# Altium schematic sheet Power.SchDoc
size A3; CompanyName: Icoteq Ltd; Address1: Cambridge House; Address2: 1 Henry Street; Address3: Bath; Address4: BA1 1BT; DocumentNumber: Power Supplies; SheetNumber: 1
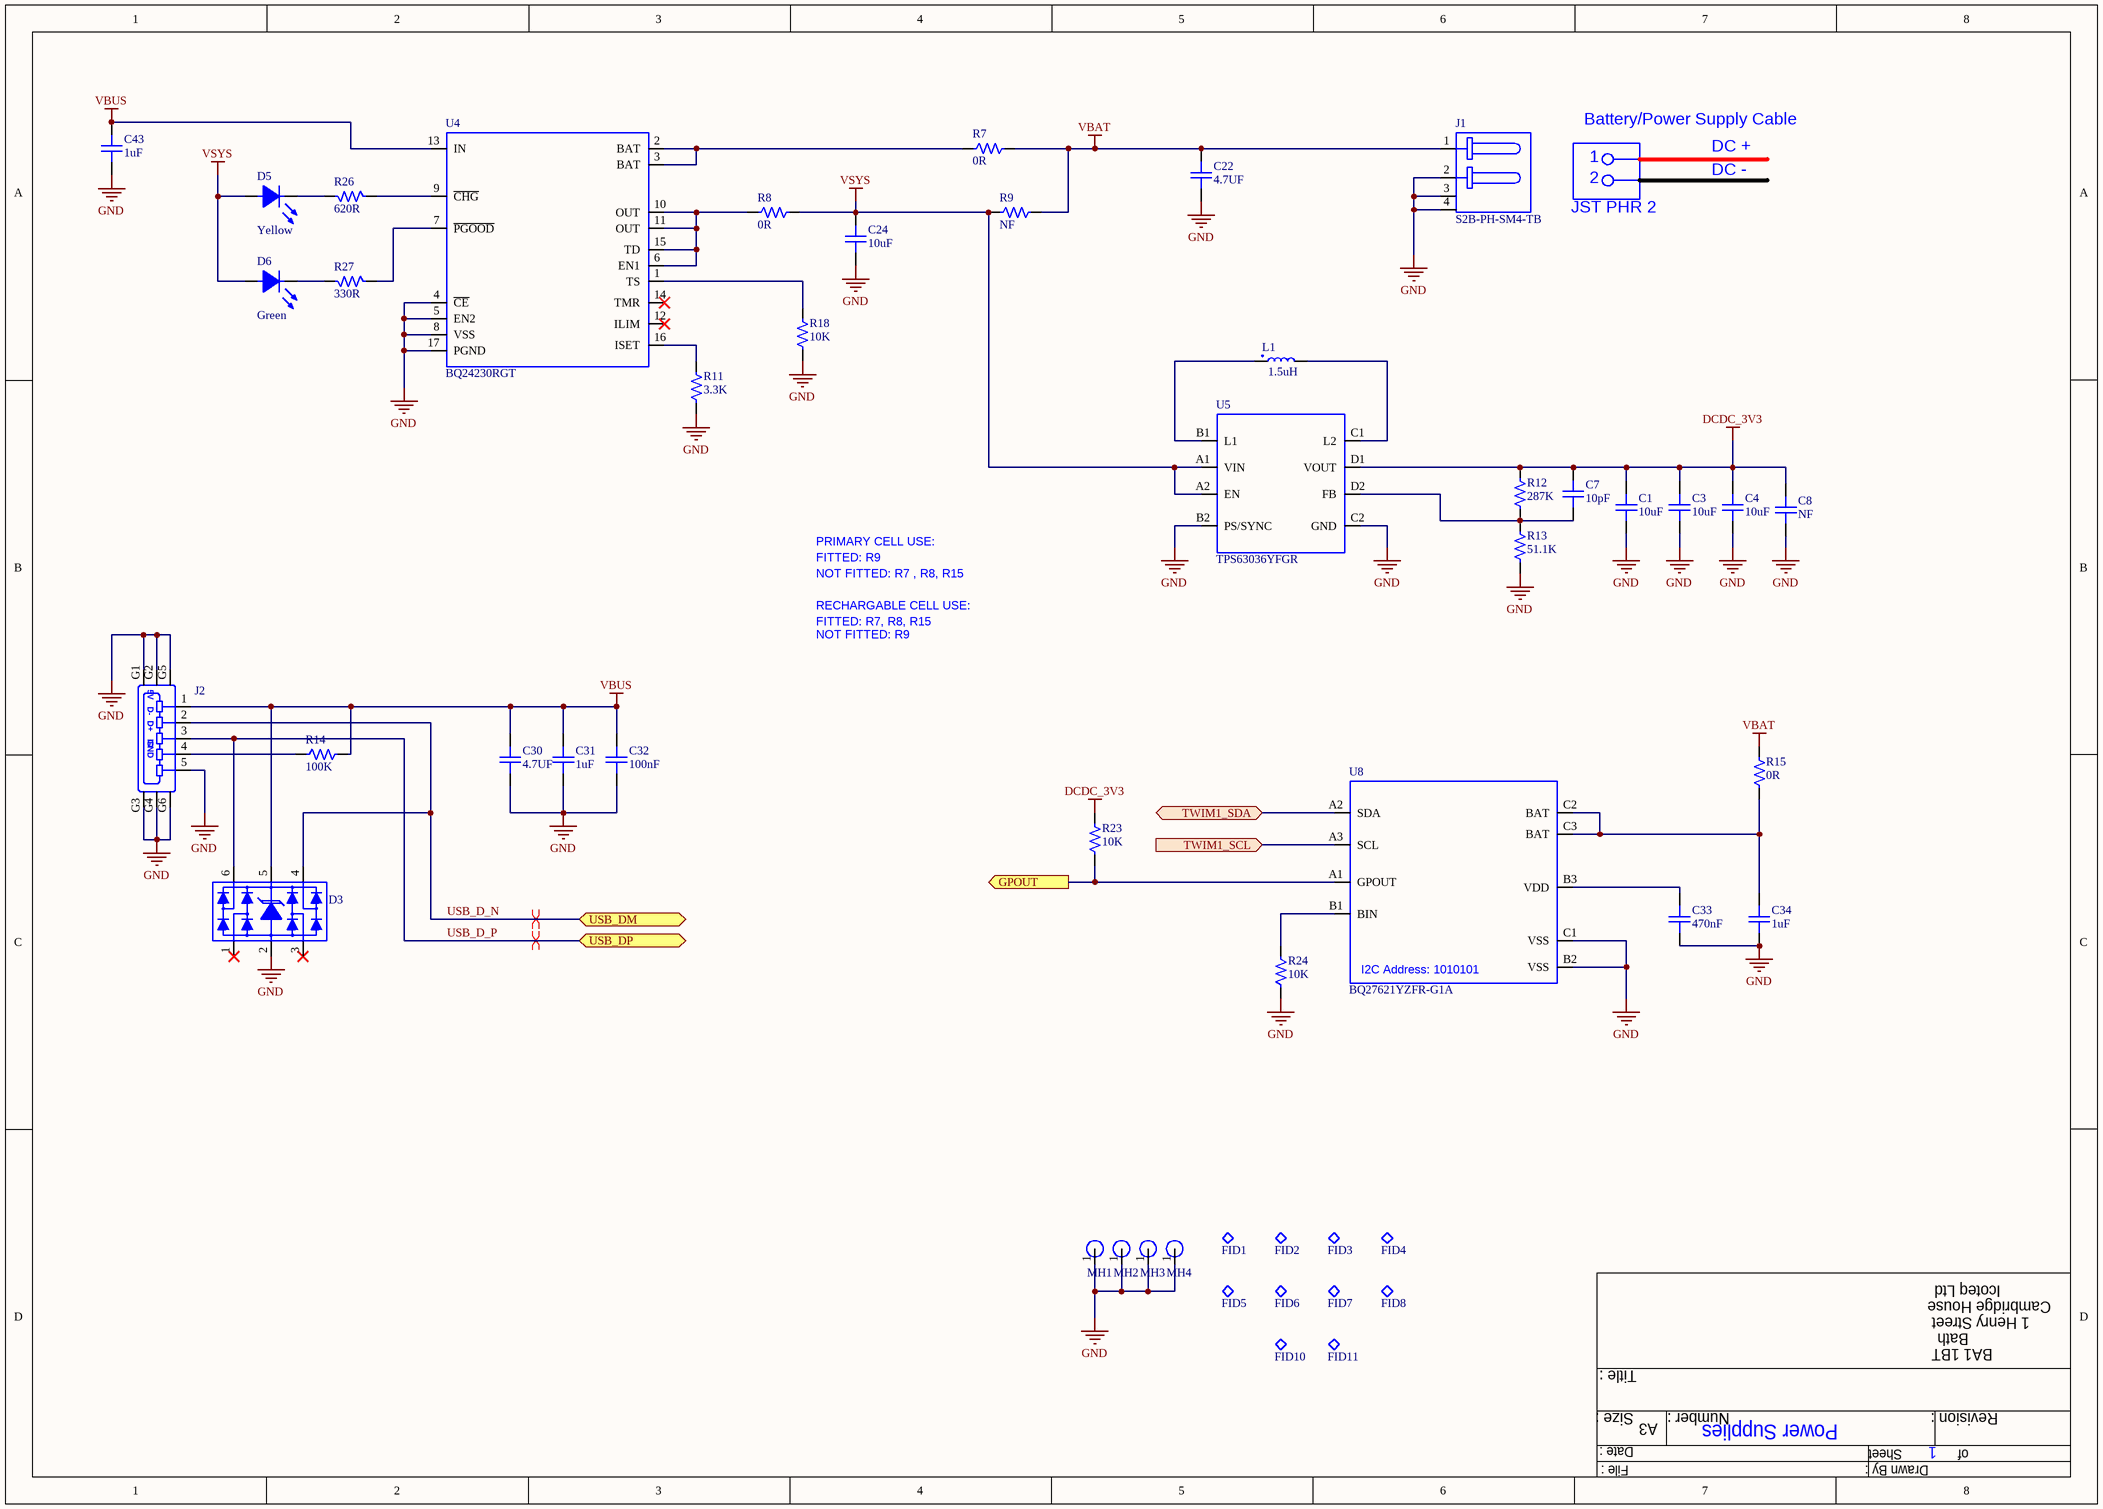
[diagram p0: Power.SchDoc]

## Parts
C1  value 10uF  [CAP0402N]  (hidden comment: 10UF 0402 6.3V 20% X5R)
C3  value 10uF  [CAP0402N]  (hidden comment: 10UF 0402 6.3V 20% X5R)
C4  value 10uF  [CAP0402N]  (hidden comment: 10UF 0402 6.3V 20% X5R)
C7  value 10pF  [Passive0201L]  (hidden comment: CAP CER 10PF 0201 25V 5% C0G)
C8  value NF  [CAP0402N_NF]  (hidden comment: CAP NF 0402)
C22  value 4.7UF  [CAP0402N]  (hidden comment: 4.7UF 0402 10V 20% X5R)
C24  value 10uF  [CAP0603N]  (hidden comment: 10UF 0603 16V 10% X5R)
C30  value 4.7UF  [CAP0402N]  (hidden comment: 4.7UF 0402 10V 20% X5R)
C31  value 1uF  [CAP0201L]  (hidden comment: 1UF 0201 10V 20% X5R)
C32  value 100nF  [CAP0201L]  (hidden comment: 100NF 0201 35V 10% X5R)
C33  value 470nF  [CAP0201L]  (hidden comment: 470NF 0201 16V 20% X5R)
C34  value 1uF  [CAP0201L]  (hidden comment: 1UF 0201 10V 20% X5R)
C43  value 1uF  [CAP0201L]  (hidden comment: 1UF 0201 10V 20% X5R)
D3  RCLAMP0504FBTCT  [SC70-6]  (value not drawn)
D5  Colour: Yellow  [DIOD0603N_YELLOW]  (hidden comment: LTST-C190KSKT)
D6  Colour: Green  [DIOD0603N_GREEN]  (hidden comment: LTST-C190KGKT)
FID1  Fiducial  [Fiducial]  (value not drawn)
FID2  Fiducial  [Fiducial]  (value not drawn)
FID3  Fiducial  [Fiducial]  (value not drawn)
FID4  Fiducial  [Fiducial]  (value not drawn)
FID5  Fiducial  [Fiducial]  (value not drawn)
FID6  Fiducial  [Fiducial]  (value not drawn)
FID7  Fiducial  [Fiducial]  (value not drawn)
FID8  Fiducial  [Fiducial]  (value not drawn)
FID10  Fiducial  [Fiducial]  (value not drawn)
FID11  Fiducial  [Fiducial]  (value not drawn)
J1  S2B-PH-SM4-TB  [SM4-2]
J2  47589-0001  [0475890001]  (value not drawn)
L1  value 1.5uH  [LPS3015 update]  (hidden comment: LPS3015-152MRC)
MH1  Mounting Hole M2 Plated  [Mounting Hole M2 Plated]  (value not drawn)
MH2  Mounting Hole M2 Plated  [Mounting Hole M2 Plated]  (value not drawn)
MH3  Mounting Hole M2 Plated  [Mounting Hole M2 Plated]  (value not drawn)
MH4  Mounting Hole M2 Plated  [Mounting Hole M2 Plated]  (value not drawn)
R7  value 0R  [RES0402N]  (hidden comment: 0R 0402)
R8  value 0R  [RES0402N]  (hidden comment: 0R 0402)
R9  value NF  [RES0402N]  (hidden comment: RES NF 0402)
R11  value 3.3K  [RES0201L]  (hidden comment: 3.3K 0201 1% 100PPM)
R12  value 287K  [RES0201N]  (hidden comment: 287K 0201 1% 100PPM)
R13  value 51.1K  [RES0201N]  (hidden comment: 51.1K 0201 1% 100PPM)
R14  value 100K  [RES0201N]  (hidden comment: 100K 0201 1% 100PPM)
R15  value 0R  [RES0402N]  (hidden comment: 0R 0402)
R18  value 10K  [RES0201L]  (hidden comment: 10K 0201 1% 100PPM)
R23  value 10K  [RES0201L]  (hidden comment: 10K 0201 1% 100PPM)
R24  value 10K  [RES0201L]  (hidden comment: 10K 0201 1% 100PPM)
R26  value 620R  [RES0201L]  (hidden comment: 620R 0201 1% 200PPM)
R27  value 330R  [RES0201L]  (hidden comment: 330R 0201 1% 100PPM)
U4  BQ24230RGT  [VQFN-16]
U5  TPS63036YFGR  [BGA8C40P2X4_108X181X62]
U8  BQ27621YZFR-G1A  [DSBGA-9]

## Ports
GPOUT (out), TWIM1_SCL (in), TWIM1_SDA (bidir), USB_DM (bidir), USB_DP (bidir)

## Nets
DCDC_3V3: C1.2 C3.2 C4.2 C7.2 C8.2 R12.2 R23.2 U5.D1(VOUT)
GND: C1.1 C3.1 C4.1 C8.1 C22.1 C24.1 C30.1 C31.1 C32.1 C33.1 C34.1 C43.1 D3.2 J1.2(GND) J1.3(GND) J1.4(GND) J2.5(GND) J2.G1 J2.G2 J2.G3 J2.G4 J2.G5 J2.G6 MH1.1 MH2.1 MH3.1 MH4.1 R11.1 R13.1 R18.1 R24.1 U4.4(~{CE}) U4.5(EN2) U4.8(VSS) U4.17(PGND) U5.B2(PS/SYNC) U5.C2(GND) U8.B2(VSS) U8.C1(VSS)
VBAT: C22.2 J1.1(DC) R7.2 R9.2 R15.2
VBUS: C30.2 C31.2 C32.2 C43.2 D3.5 J2.1(5V) R14.2 U4.13(IN)
VSYS: C24.2 D5.1 D6.1 R8.2 R9.1 U5.A1(VIN) U5.A2(EN)
GPOUT: R23.1 U8.A1(GPOUT) ; port GPOUT
TWIM1_SCL: U8.A3(SCL) ; port TWIM1_SCL
TWIM1_SDA: U8.A2(SDA) ; port TWIM1_SDA
USB_D_N: D3.4 J2.2(D-) ; port USB_DM
USB_D_P: D3.6 J2.3(D+) ; port USB_DP
NetC7_1: C7.1 R12.1 R13.2 U5.D2(FB)
NetC33_2: C33.2 U8.B3(VDD)
NetC34_2: C34.2 R15.1 U8.C2(BAT) U8.C3(BAT)
NetD5_2: D5.2 R26.2
NetD6_2: D6.2 R27.2
NetJ2_4: J2.4(ID) R14.1
NetL1_1: L1.1 U5.B1(L1)
NetL1_2: L1.2 U5.C1(L2)
NetR7_1: R7.1 U4.2(BAT) U4.3(BAT)
NetR8_1: R8.1 U4.6(EN1) U4.10(OUT) U4.11(OUT) U4.15(TD)
NetR11_2: R11.2 U4.16(ISET)
NetR18_2: R18.2 U4.1(TS)
NetR24_2: R24.2 U8.B1(BIN)
NetR26_1: R26.1 U4.9(~{CHG})
NetR27_1: R27.1 U4.7(~{PGOOD})

Not connected (* = marked no-connect by the designer): D3 1* 3*; U4 12(ILIM)* 14(TMR)*

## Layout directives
differential pair: USB_D_N, USB_D_P

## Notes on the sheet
- Battery/Power Supply Cable
- 1
- DC +
- DC -
- JST PHR 2
- 2
- PRIMARY CELL USE:
- FITTED: R9
- NOT FITTED: R7 , R8, R15
- RECHARGABLE CELL USE:
- FITTED: R7, R8, R15
- NOT FITTED: R9

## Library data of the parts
C1 C3 C4 = CAP CER 10UF 0402 6.3V 20% X5R: Manufacturer: Taiyo Yuden; Manufacturers Part Number: JMK105CBJ106MV-F
C7 = CAP CER 10PF 0201 25V 5% C0G: Manufacturer: Murata; Manufacturers Part Number: GRM0335C1E100JA01D
C8 = CAP NF 0402: Manufacturer: NOT FITTED PART
C22 C30 = CAP CER 4.7UF 0402 10V 20% X5R: Manufacturer: TDK; Manufacturers Part Number: C1005X5R1A475M050BC
C24 = CAP CER 10UF 0603 16V 10% X5R: Manufacturer: Murata; Manufacturers Part Number: GRT188R61C106KE13D
C31 C34 C43 = CAP CER 1UF 0201 10V 20% X5R: Manufacturer: Murata; Manufacturers Part Number: GRM033R61A105ME15D
C32 = CAP CER 100NF 0201 35V 10% X5R: Manufacturer: Murata; Manufacturers Part Number: GRM033R6YA104KE14D
C33 = CAP CER 470NF 0201 16V 20% X5R: Manufacturer: Taiyo Yuden; Manufacturers Part Number: EMK063BBJ474MPLF
D3 = RCLAMP0504FBTCT: DIO ARRAY ESD; Manufacturer: Semtech
D5 = LED YELLOW 0603 20MA VF=2V: Manufacturer: Lite-On Inc
D6 = LED GREEN 0603 20MA VF=2V: Manufacturer: Lite-On Inc
FID1-FID8 FID10 FID11 = Fiducial: Manufacturer: NOT FITTED PART
J1 = CON HDR 2POS 2.0MM PITCH: Manufacturer: JST Sales America; Manufacturers Part Number: S2B-PH-SM4-TB(LF)(SN); Frequency Range: DC
J2 = CON MICRO USB 2.0 TYPE AB R/A SMD: Manufacturer: Molex
L1 = IND PWR 1.5UH 20% 1.7A 2.95MM x 2.95MM x 1.4MM: Manufacturer: Coilcraft
MH1-MH4 = Mounting Hole M2 Plated: Manufacturer: NOT FITTED PART
R7 R8 R15 = RES 0R 0402
R9 = RES NF 0402: Manufacturer: NOT FITTED PART
R11 = RES 3.3K 0201 1% 100PPM: PPM: 100
R12 = RES 287K 0201 1% 100PPM: PPM: 100
R13 = RES 51.1K 0201 1% 100PPM: PPM: 100
R14 = RES 100K 0201 1% 100PPM: PPM: 100
R18 R23 R24 = RES 10K 0201 1% 100PPM: PPM: 100
R26 = RES 620R 0201 1% 200PPM: PPM: 200
R27 = RES 330R 0201 1% 100PPM: PPM: 100
U4 = BQ24230RGT: IC BATT CHG LI ION 4.2V (IP 4.3 - 6.5V) 500MA; Manufacturer: Texas Instruments; Manufacturers Part Number: BQ24230RGTR
U5 = TPS63036YFGR: IC VREG BUCK BOOST 500mA IP 1.8V-5.5V ADJ; Manufacturer: Texas Instruments
U8 = BQ27621YZFR-G1A: IC BATT MGMT 2.45V - 4.5V DSBGA-9; Manufacturer: Texas Instruments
